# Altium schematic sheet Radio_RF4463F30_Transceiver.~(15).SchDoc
size A4
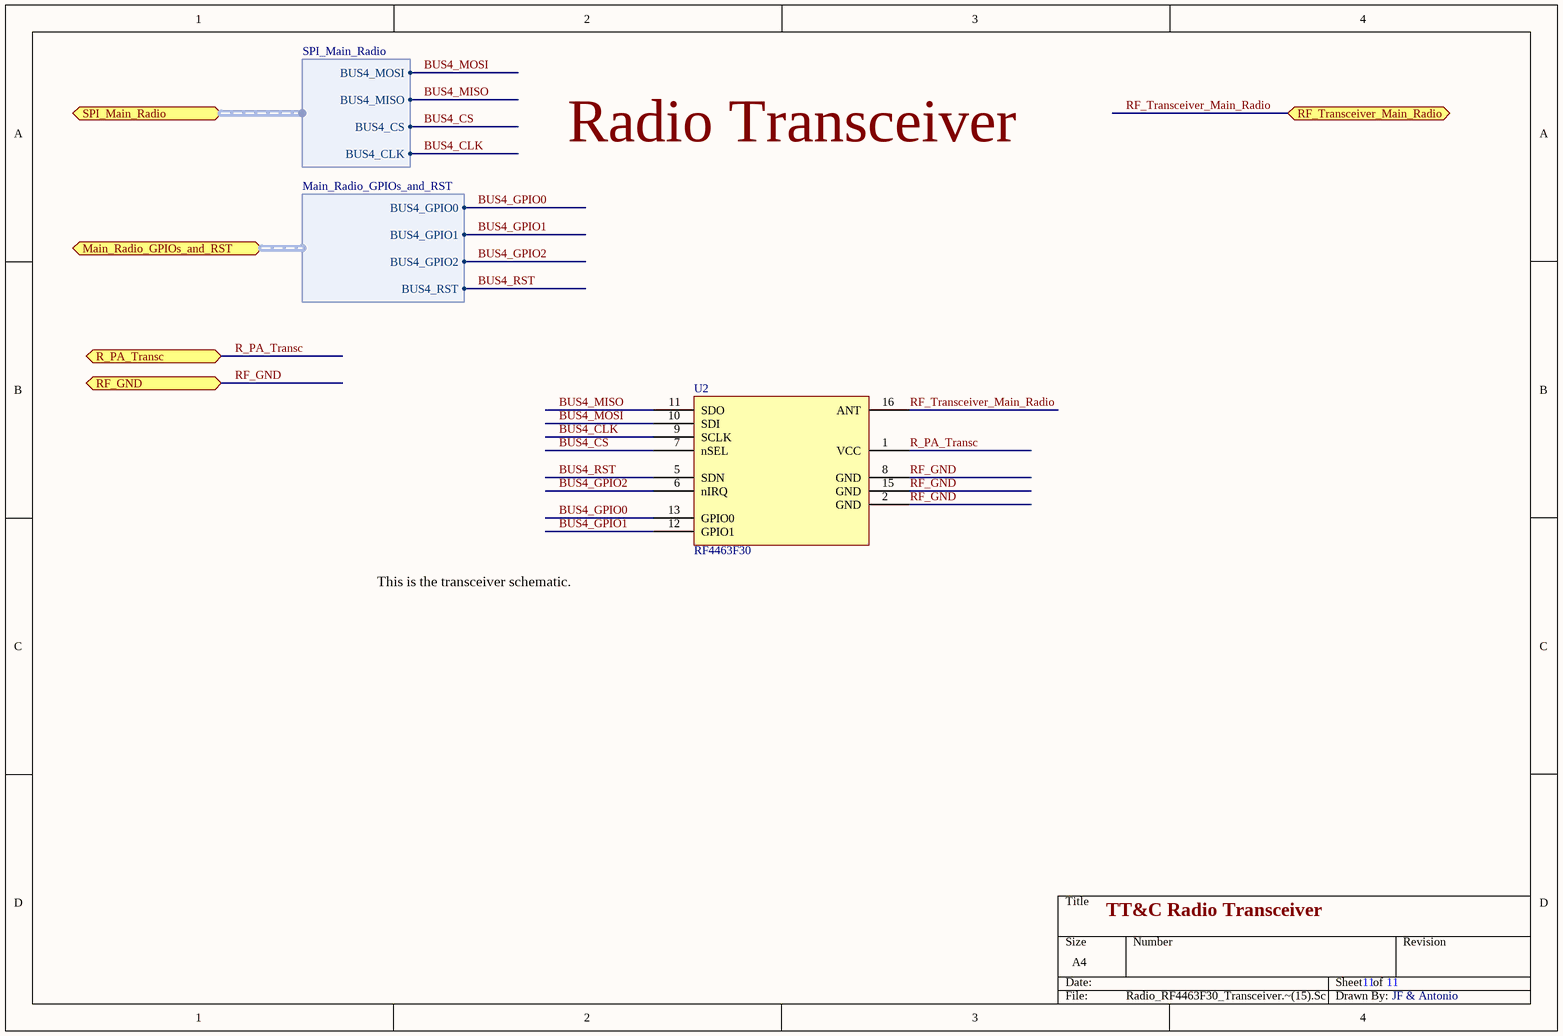
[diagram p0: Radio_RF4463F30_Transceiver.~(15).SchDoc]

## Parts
U2  RF4463F30

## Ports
Main_Radio_GPIOs_and_RST (harness Main_Radio_GPIOs_and_RST), R_PA_Transc, RF_GND, RF_Transceiver_Main_Radio, SPI_Main_Radio (harness SPI_Main_Radio)

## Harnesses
SPI_Main_Radio: BUS4_MOSI, BUS4_MISO, BUS4_CS, BUS4_CLK
Main_Radio_GPIOs_and_RST: BUS4_GPIO0, BUS4_GPIO1, BUS4_GPIO2, BUS4_RST

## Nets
BUS4_CLK: U2.9(SCLK) ; port SPI_Main_Radio.BUS4_CLK
BUS4_CS: U2.7(nSEL) ; port SPI_Main_Radio.BUS4_CS
BUS4_GPIO0: U2.13(GPIO0) ; port Main_Radio_GPIOs_and_RST.BUS4_GPIO0
BUS4_GPIO1: U2.12(GPIO1) ; port Main_Radio_GPIOs_and_RST.BUS4_GPIO1
BUS4_GPIO2: U2.6(nIRQ) ; port Main_Radio_GPIOs_and_RST.BUS4_GPIO2
BUS4_MISO: U2.11(SDO) ; port SPI_Main_Radio.BUS4_MISO
BUS4_MOSI: U2.10(SDI) ; port SPI_Main_Radio.BUS4_MOSI
BUS4_RST: U2.5(SDN) ; port Main_Radio_GPIOs_and_RST.BUS4_RST
R_PA_Transc: U2.1(VCC) ; port R_PA_Transc
RF_GND: U2.2(GND) U2.8(GND) U2.15(GND) ; port RF_GND
RF_Transceiver_Main_Radio: U2.16(ANT) ; port RF_Transceiver_Main_Radio

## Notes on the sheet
- Radio Transceiver
- (near U2) This is the transceiver schematic.
- TT&C Radio Transceiver
- 11
- JF & Antonio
